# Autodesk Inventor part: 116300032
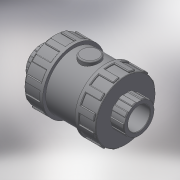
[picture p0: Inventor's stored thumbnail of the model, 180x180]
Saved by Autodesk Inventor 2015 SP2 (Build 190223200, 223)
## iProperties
Created: 2017-11
Part Number: 116300032
Material: Generic
Description: PLASSON AIR RELEASE VALVE CEM PVC 32
Document SubType Name: Modeling
Designer: KIM
Density: 1 g/cm^3
Appearance: Default
Author: KIM
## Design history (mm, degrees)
derived "116300 - 116900.ipt"
feature "Solid1::116300 - 116900.ipt"
tag "TaggingFeature1"
body "Solid1"
other parameters: "d0" = 102, "d1" = 32, "d2" = 66, "d3" = 22, "d4" = 25.6, "d5" = 15.4, "d7" = 44.8, "d8" = 59.4, "d13" = 0.96, "d23" = 22, "d24" = 63.36, "d25" = 0.64, "d26" = 0.96, "d27" = 9.9, "d28" = 4.95, "d29" = 16.5, "d30" = 0, "d35" = 0.96, "d39" = 33, "d45" = 360 deg, "d47" = 0.64, "d50" = 33, "d51" = 19.8, "d53" = 0, "d54" = 1.32, "d55" = 6.4, "d56" = 3.2, "d58" = 0, "d59" = 0.96, "d61" = 360 deg, "d_" = 32, "l_" = 22, "H_" = 102, "K_" = 66
